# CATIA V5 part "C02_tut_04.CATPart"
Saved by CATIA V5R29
Part number: Part1
Bounding box of the stored display mesh (mm): x 0 to 0, y -49.55 to 100.45, z -30 to 49.981
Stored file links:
  D:\Abhinav\2019\3rd Session\CATIA V5 2019\RESOURCES\CATIA_RESOURCES\Tutorial Files\Tutorials\Tutorials\c02_catia_v5_6r2019_tut\c02_catia_v5_6r2019_tut\c02_catia_v5_6r2019_tut\C02_tut_04.CATPart
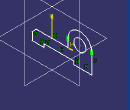
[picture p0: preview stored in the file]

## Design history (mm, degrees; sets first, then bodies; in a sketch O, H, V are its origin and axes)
Body1 (main body)
  Sketch1 on yz-plane, origin (0, 0, 0), H (0, 1, 0), V (0, 0, 1)
    line L1 (-49.55, -30) -> (-20, -30)
    line L2 (-20, -30) -> (-20, -22)
    line L3 (-20, -22) -> (55, -22)
    line L4 (55, -22) -> (55, -30)
    line L5 (55, -30) -> (55.45, -30)
    line L6 (55.45, -30) -> (100.45, -30)
    line L7 (100.45, -30) -> (100.45, 20)
    arc A1 centre (70.45, 20) radius 30 from (100.45, 20) to (40.45, 20) ccw
    line L8 (40.45, 20) -> (40.45, 0)
    line L9 (40.45, 0) -> (-39.55, 0)
    line L10 (-39.55, 0) -> (-49.55, -10)
    line L11 (-49.55, -10) -> (-49.55, -30)
    circle A2 centre (70.45, 20) radius 15
    horizontal: L1 H, L3 H, L5 H, L6 H, L9 H
    vertical: L2 V, L4 V, L7 V, L11 V
    tangency: A1 L7, L8 A1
